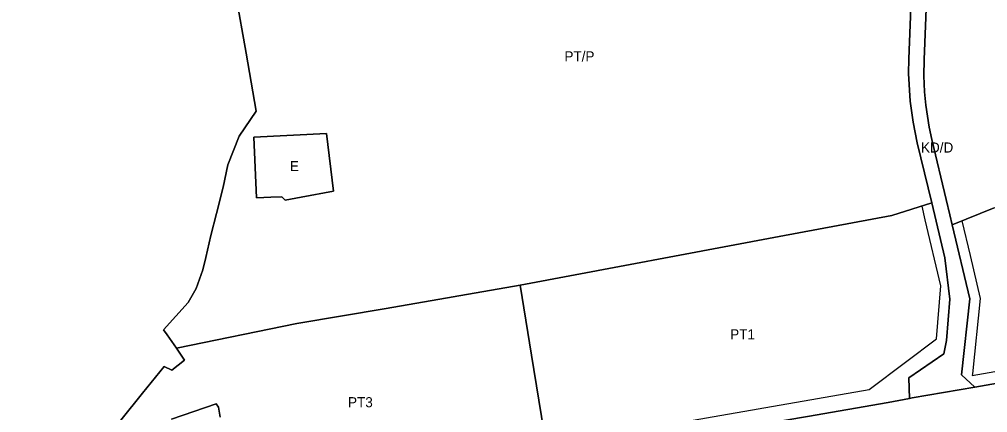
# Model space of a CAD drawing. Extents: x 7436680 to 7439366, y 5548361 to 5550775.
# Drawn here: x 7437475 to 7438434, y 5549127 to 5549516 of the extents above; entities that cross this region are included whole.
import ezdxf

# ---------------------------------------------------------------- set-up
doc = ezdxf.new("R2010")
doc.units = 0
for name, color, linetype in [('linie_rozgraniczajace', 7, 'Continuous'), ('linie_zabudowy_nieprzekraczalne', 7, 'Continuous'), ('oznaczenia_przeznaczen', 7, 'Continuous')]:
    doc.layers.add(name, color=color, linetype=linetype)

msp = doc.modelspace()

# ---------------------------------------------------------------- linework, layer by layer
at = {"layer": 'linie_rozgraniczajace'}
for points in [[(7438363.8, 5549687.79), (7438355.78, 5549477.05), (7438355.24, 5549462.75), (7438357.04, 5549435.24), (7438359.98, 5549414.6), (7438363.96, 5549393.99), (7438378.49, 5549334.48), (7438338.8, 5549322.13), (7438227.34, 5549301.19), (7437970.79, 5549253.27), (7437838.03, 5549230.1), (7437749.69, 5549215.27), (7437630.49, 5549190.67), (7437621.18, 5549204.06), (7437617.74, 5549209), (7437629.86, 5549222.43), (7437641.98, 5549235.87), (7437650.03, 5549249.74), (7437656.75, 5549268.41), (7437659.47, 5549280.51), (7437664.67, 5549302.45), (7437670.08, 5549324.02), (7437676.62, 5549350.07), (7437681.29, 5549372.16), (7437686.92, 5549386.4), (7437692.54, 5549400.64), (7437709.51, 5549425.53), (7437699.39, 5549482.97), (7437689.27, 5549540.41)], [(7438373, 5549535.1), (7438370.77, 5549476.48), (7438370.67, 5549460.25), (7438371.24, 5549444.64), (7438372.44, 5549431.17), (7438375.66, 5549409.56), (7438378.55, 5549397.47), (7438392.73, 5549338.03), (7438396.37, 5549322.74), (7438398.71, 5549312.9), (7438416.17, 5549239.74), (7438407.75, 5549164.35), (7438420.86, 5549152.06), (7438358.93, 5549141.46), (7438356.27, 5549140.95), (7438355.6, 5549161.53), (7438390.24, 5549185.26), (7438392.82, 5549198.47), (7438396.35, 5549239.37), (7438391.14, 5549280.09), (7438378.49, 5549334.48), (7438363.96, 5549393.99), (7438359.98, 5549414.6), (7438357.04, 5549435.24), (7438355.24, 5549462.75), (7438355.78, 5549477.05), (7438363.8, 5549687.79)], [(7438440, 5549329.59), (7438398.71, 5549312.9), (7438396.37, 5549322.74), (7438392.73, 5549338.03), (7438378.55, 5549397.47), (7438375.66, 5549409.56), (7438372.44, 5549431.17), (7438371.24, 5549444.64), (7438370.67, 5549460.25), (7438370.77, 5549476.48), (7438373, 5549535.1), (7438374.79, 5549593.74), (7438447.12, 5549603.43)], [(7437689.27, 5549540.41), (7437699.39, 5549482.97), (7437709.51, 5549425.53), (7437692.54, 5549400.64), (7437686.92, 5549386.4), (7437681.29, 5549372.16), (7437676.62, 5549350.07), (7437670.08, 5549324.02), (7437664.67, 5549302.45), (7437659.47, 5549280.51), (7437656.75, 5549268.41), (7437650.03, 5549249.74), (7437641.98, 5549235.87), (7437629.86, 5549222.43), (7437617.74, 5549209), (7437621.18, 5549204.06), (7437630.49, 5549190.67), (7437638.54, 5549178.77), (7437625.9, 5549168.99), (7437618.36, 5549172.57), (7437596.84, 5549146.06), (7437575.32, 5549119.55)], [(7437575.32, 5549119.55), (7437596.84, 5549146.06), (7437618.36, 5549172.57), (7437625.9, 5549168.99), (7437638.54, 5549178.77), (7437630.49, 5549190.67), (7437749.69, 5549215.27), (7437838.03, 5549230.1), (7437970.79, 5549253.27), (7437982.05, 5549183.92), (7437999.18, 5549078.49)], [(7437471.46, 5549022.59), (7437478.39, 5549011.74), (7437481.28, 5549007.22), (7437496.12, 5549002.15), (7437548.26, 5549000.19), (7437570.44, 5549003.41), (7437657.52, 5549018.7), (7437677.73, 5549022.24), (7437679.21, 5549022.5), (7437786.66, 5549040.99), (7437856.52, 5549053.27), (7437999.18, 5549078.49), (7438038.34, 5549085.45), (7438100.24, 5549096.55), (7438167.47, 5549108.23), (7438255.31, 5549123.14), (7438335.28, 5549136.91), (7438356.27, 5549140.95), (7438358.93, 5549141.46), (7438420.86, 5549152.06), (7438591.21, 5549182.25)], [(7437625.68, 5549120.51), (7437669.71, 5549135.8), (7437672.21, 5549132.35), (7437673.64, 5549122.45)], [(7437673.64, 5549122.45), (7437672.21, 5549132.35), (7437669.71, 5549135.8), (7437625.68, 5549120.51)]]:
    msp.add_lwpolyline(points, dxfattribs=at)
for points in [[(7437707.2, 5549399.8), (7437709.85, 5549339.71), (7437716.96, 5549339.9), (7437724.08, 5549340.09), (7437734.95, 5549340.7), (7437738.03, 5549337.3), (7437753.88, 5549340.15), (7437785.88, 5549346.11), (7437779.2, 5549403.34)], [(7437707.2, 5549399.8), (7437779.2, 5549403.34), (7437785.88, 5549346.11), (7437753.88, 5549340.15), (7437738.03, 5549337.3), (7437734.95, 5549340.7), (7437724.08, 5549340.09), (7437716.96, 5549339.9), (7437709.85, 5549339.71)], [(7438398.71, 5549312.9), (7438440, 5549329.59), (7438519.44, 5549349.55), (7438518.12, 5549335.61), (7438563.16, 5549343.44), (7438591.21, 5549182.25), (7438420.86, 5549152.06), (7438407.75, 5549164.35), (7438416.17, 5549239.74)], [(7437970.79, 5549253.27), (7438227.34, 5549301.19), (7438338.8, 5549322.13), (7438378.49, 5549334.48), (7438391.14, 5549280.09), (7438396.35, 5549239.37), (7438392.82, 5549198.47), (7438390.24, 5549185.26), (7438355.6, 5549161.53), (7438356.27, 5549140.95), (7438335.28, 5549136.91), (7438255.31, 5549123.14), (7438167.47, 5549108.23), (7438100.24, 5549096.55), (7438038.34, 5549085.45), (7437999.18, 5549078.49), (7437982.05, 5549183.92)]]:
    msp.add_lwpolyline(points, close=True, dxfattribs=at)
at = {"layer": 'linie_zabudowy_nieprzekraczalne'}
for points in [[(7438408.09, 5549316.69), (7438416.26, 5549282.45), (7438426.4, 5549239.95), (7438418.62, 5549165.26), (7438418.46, 5549163.74), (7438586.64, 5549193.27), (7438761.68, 5549222.25), (7438868.34, 5549239.99), (7438975, 5549257.73), (7439006.9, 5549266.48), (7439040.16, 5549312.18), (7439048.44, 5549320.99), (7439087.26, 5549346.27), (7439087.48, 5549364.08), (7439084.43, 5549411.4), (7439081.38, 5549458.72)], [(7438352.43, 5549177), (7438382.9, 5549199.87), (7438387.45, 5549252.46), (7438371.87, 5549317.76), (7438368.9, 5549331.5)], [(7438316.41, 5549149.98), (7438352.43, 5549177)], [(7437672.18, 5549037.52), (7438316.41, 5549149.98)]]:
    msp.add_lwpolyline(points, dxfattribs=at)

# ---------------------------------------------------------------- texts
at = {"layer": 'oznaczenia_przeznaczen'}
for s, p in [('PT/P', (7438014.65, 5549474.63)), ('KD/D', (7438367.7, 5549384.42)), ('E', (7437742.88, 5549366)), ('PT1', (7438178.78, 5549199.43)), ('PT3', (7437800.37, 5549132.25))]:
    msp.add_text(s, height=10, dxfattribs=at).set_placement(p)

doc.saveas('drawing.dxf')
